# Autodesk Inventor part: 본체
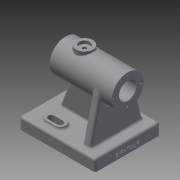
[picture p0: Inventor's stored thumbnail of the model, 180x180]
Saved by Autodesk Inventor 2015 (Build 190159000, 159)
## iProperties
Created: 2022-06
Part Number: 본체
Material: 일반
Document SubType Name: Modeling
Designer: 104-1
Density: 1 g/cm^3
Appearance: 기본값
Author: 104-1
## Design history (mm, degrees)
sketch "스케치1"
  geometry: L1 (-50, -43)-(50, -43); L2 (50, -43)-(50, 43); L3 (50, 43)-(-50, 43); L4 (-50, 43)-(-50, -43); L5 (-50, -43)-(50, 43); L6 (50, -43)-(-50, 43); 1 further point
  constraints: 12 end point, 2 midpoint, 2 parallel, 1 horizontal, 1 perpendicular
  dimensions: "d0" = 100 distance of L2.end L3.end; "d1" = 86 distance of L1.end L2.end
extrude "돌출1" new body sketch "스케치1" distance "d2" = 15; taper "d3" = 0 deg
sketch "스케치3"
  geometry: L1 (50, -43)-(50, 43) reference; L2 (50, 43)-(-50, 43) reference; L3 (-50, 43)-(-50, -43) reference; L4 (25, 35)-(35, 35); L5 (35, 35)-(35, -35); L6 (35, -35)-(25, -35); L7 (25, -35)-(25, 35); L8 (-35, 5)-(35, 5); L9 (35, 5)-(35, -5); L10 (35, -5)-(-35, -5); L11 (-35, -5)-(-35, 5); L12 (-50, 0)-(50, 0); 1 further point
  constraints: 18 end point, 4 parallel, 2 horizontal, 2 midpoint, 2 perpendicular, 2 other
  dimensions: "d4" = 15 distance between parallel lines of L1 L5; "d5" = 15 distance between parallel lines of L1 L9; "d6" = 10 distance of L4.start L4.end; "d7" = 10 distance of L10.end L8.start; "d8" = 15 distance between parallel lines of L3 L11; "d9" = 8 distance between parallel lines of L2 L4
extrude "돌출2" join sketch "스케치3" distance "d10" = 57; taper "d11" = 0 deg
sketch "스케치4"
  geometry: L1 (50, 43)-(-50, 43) reference; L2 (-50, 43)-(-50, -43) reference; L3 (-31, 20)-(-5, 20); L4 (-5, 20)-(-5, 34); L5 (-5, 34)-(-31, 34); L6 (-31, 34)-(-31, 20); L7 (-31, 20)-(-5, 34); L8 (-5, 20)-(-31, 34); L9 (-24, 34)-(-12, 34); L10 (-24, 20)-(-12, 20); A1 r 7 centre (-24, 27) between (-24, 34) and (-24, 20); A2 r 7 centre (-12, 27) between (-18.98, 27.528) and (-18.98, 26.472); A3 r 7 centre (-12, 27) between (-12, 20) and (-12, 34); 4 further points
  constraints: 16 end point, 6 point on circle, 6 point on line, 3 centre point, 2 coincident, 2 horizontal alignment, 2 midpoint, 2 parallel, 1 horizontal, 1 perpendicular, 1 tangent
  dimensions: "d12" = 26 distance from line of point (-24, 27) L2; "d13" = 16 distance from line of L1 point (-24, 27); "d14" = 12 distance of point (-12, 27) point (-24, 27); "d15" = 6 distance of point (-18, 27) point (-24, 27); "d16" = 26 distance of L4.end L5.end; "d17" = 14 distance of L3.end L4.end
extrude "돌출3" join sketch "스케치4" distance "d19" = 3; taper "d20" = 0 deg
sketch "스케치5"
  geometry: L1 (-12, 34)-(-24, 34) reference; L2 (-24, 20)-(-12, 20) reference; L3 (-24, 31)-(-12, 31); L4 (-12, 23)-(-24, 23); A1 r 7 centre (-12, 27) between (-12, 20) and (-12, 34) reference; A2 r 7 centre (-24, 27) between (-24, 34) and (-24, 20) reference; A3 r 4 centre (-24, 27) between (-24, 31) and (-24, 23); A4 r 4 centre (-12, 27) between (-12, 23) and (-12, 31); 1 further point
  constraints: 4 end point, 4 point on circle, 2 centre point, 3 other
  dimensions: "d21" = 3 radial gap between concentric circles of A2 A3
extrude "돌출4" cut sketch "스케치5" stored distance "d22" = 3; taper "d23" = 0 deg
sketch "스케치7"
  geometry: L1 (0, 10)-(0, 0) reference; L2 (0, 10)-(-57, 10) reference; L3 (-57, 0)-(-57, 10) reference; L4 (0, 0)-(-57, 0) reference; L5 (15, -38)-(0, -38) reference; L6 (0, 48)-(0, -38) reference; L7 (0, -30)-(-61.814, -15.441); L8 (0, 40)-(-61.814, 25.441); L9 (-61.814, -15.441)-(-61.814, 25.441); L10 (0, -30)-(0, 40); A1 r 21 centre (-57, 5) between (-61.814, -15.441) and (-61.814, 25.441); 1 further point
  constraints: 8 end point, 2 point on circle, 2 tangent, 1 centre point, 1 midpoint, 1 point on line, 1 vertical, 1 vertical alignment
  dimensions: "d25" = 42 diameter of A1; "d26" = 8 distance from line of L7.start L5; "d27" = 8 distance of L6.start L8.start
extrude "돌출5" join sketch "스케치7" distance "d28" = 10; taper "d29" = 0 deg
feature "면 기울기1" dims angle "d30" = 20 deg
fillet "모깎기1" dims "d31" = 3
sketch "스케치8"
  geometry: L1 (32, 93)-(-50, 93); L2 (-50, 93)-(-50, 72); L3 (-50, 72)-(32, 72); L4 (32, 72)-(32, 93); L5 (-50, 0)-(-50, 15) reference; L6 (-50, 15)-(-35, 15) reference; L7 (-35, 15)-(-35, 76.814) reference; L8 (-35, 76.814)-(-25, 76.814) reference; L9 (-25, 76.814)-(-25, 72) reference; L10 (-25, 72)-(14.254, 72) reference; L11 (14.254, 72)-(35, 15) reference; L12 (35, 15)-(50, 15) reference; L13 (50, 15)-(50, 0) reference; L14 (50, 0)-(-50, 0) reference; L15 (-50, 0)-(-50, 15) reference; 2 further points
  constraints: 8 end point, 2 parallel, 1 horizontal, 1 midpoint, 1 perpendicular, 1 point on line
  dimensions: "d32" = 21 distance of L1.end L2.end; "d33" = 82 distance of L1.start L1.end; "d34" = 0 distance between parallel lines of L5 L2
revolve "회전1" sketch "스케치8" stored, may be unused: angle "d35" = 90 deg
fillet "모깎기2" dims "d36" = 3
fillet "모깎기3" dims "d37" = 3
sketch "스케치9"
  geometry: C1 r 21 at (0, 0) reference; 1 further point
hole "구멍1" sketch "스케치9" at (0, 0) diameter "d38" = 23; stored, may be unused: countersink angle "d42" = 90 deg, drill point angle "d44" = 0 deg; dims "d39" = 6, "d40" = 29, "d41" = 62, "d43" = 82
node "작업 평면1"
sketch "스케치10"
  geometry: L1 (-32, 21)-(-32, -21) reference; C1 r 11 at (-7, 0); 1 further point
  constraints: 1 centre point
  dimensions: "d46" = 25 distance from line of C1.centre L1; "d47" = 22 diameter of C1
extrude "돌출6" join sketch "스케치10" stored distance "d48" = 82; taper "d49" = 0 deg
sketch "스케치11"
  geometry: C1 r 11 at (0, 0) reference; 1 further point
hole "구멍2" sketch "스케치11" at (0, 0) diameter "d50" = 14; stored, may be unused: countersink angle "d54" = 90 deg, drill point angle "d56" = 0 deg; dims "d51" = 6, "d52" = 29, "d53" = 62, "d55" = 4
sketch "스케치12"
  geometry: 2 further points
  constraints: 1 horizontal alignment
hole "구멍3" sketch "스케치12" at (0, 0) diameter "d57" = 4.917; stored, may be unused: countersink angle "d61" = 90 deg, drill point angle "d63" = 0 deg; dims "d58" = 10, "d59" = 29, "d60" = 62, "d62" = 10
sketch "스케치13"
  geometry: C1 r 14.5 at (0, 0) reference; 2 further points
  dimensions: "d64" = 18 distance of C1.centre point (18, 0)
hole "구멍4" sketch "스케치13" at (18, 0) diameter "d65" = 2.459; stored, may be unused: countersink angle "d69" = 90 deg, drill point angle "d71" = 118 deg; dims "d66" = 8, "d67" = 29, "d68" = 62, "d70" = 10
sketch "스케치14"
  geometry: C1 r 11.5 at (0, 0) reference; 2 further points
  constraints: 1 horizontal alignment
  dimensions: "d75" = 18 distance of C1.centre point (-18, 0)
hole "구멍5" sketch "스케치14" at (-18, 0) diameter "d76" = 2.459; stored, may be unused: countersink angle "d80" = 90 deg, drill point angle "d82" = 118 deg; dims "d77" = 8, "d78" = 29, "d79" = 62, "d81" = 10
fillet "모깎기4" dims "d86" = 1
fillet "모깎기5" dims "d87" = 3
fillet "모깎기6" dims "d88" = 3
sketch "스케치15"
  geometry: L1 (0, 0)-(0, 80) reference; 3 further points
  constraints: 1 horizontal alignment, 1 midpoint, 1 other
  dimensions: "d89" = 6 distance of point (0, 40) point (-6, 40)
feature "엠보싱1" sketch "스케치15" dims "d0" = 100, "d1" = 86, "d5" = 15, "d90" = 0.5, "d91" = 0
fillet "모깎기7" dims "d92" = 3
fillet "모깎기8" dims "d93" = 3
node "솔리드1"
mirror "대칭1"
pattern_circular "원형 패턴1" dims angle "d73" = 360 deg
pattern_circular "원형 패턴2" dims angle "d84" = 360 deg
node "절단 모서리 투영1"
other parameters: "d18" = 14, "d45" = 96
